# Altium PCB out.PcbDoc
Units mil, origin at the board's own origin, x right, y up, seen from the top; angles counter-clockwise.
Board outline 6000 x 4000 mil, 2 copper layers (Top Layer, Bottom Layer); 0 components, 0 nets, 40 pads, 0 vias.
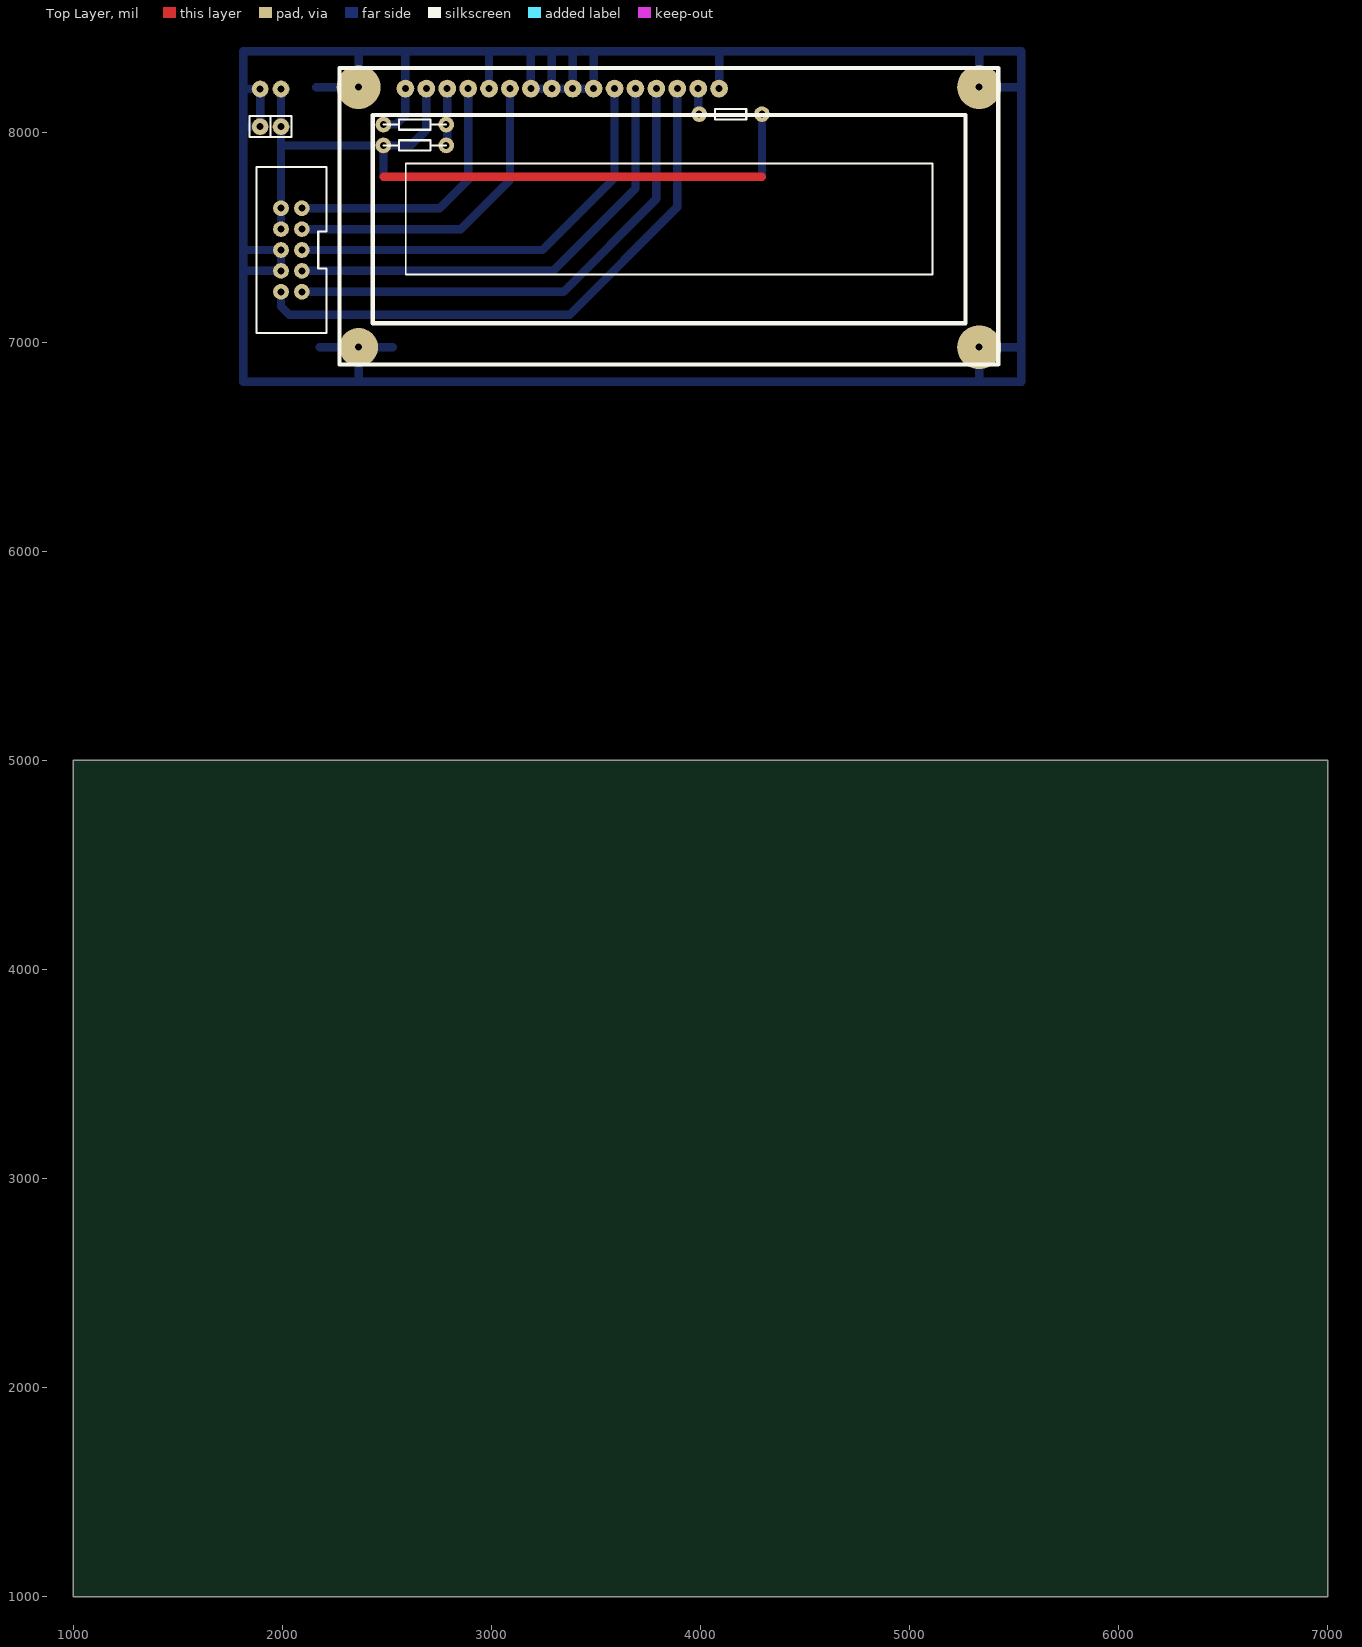
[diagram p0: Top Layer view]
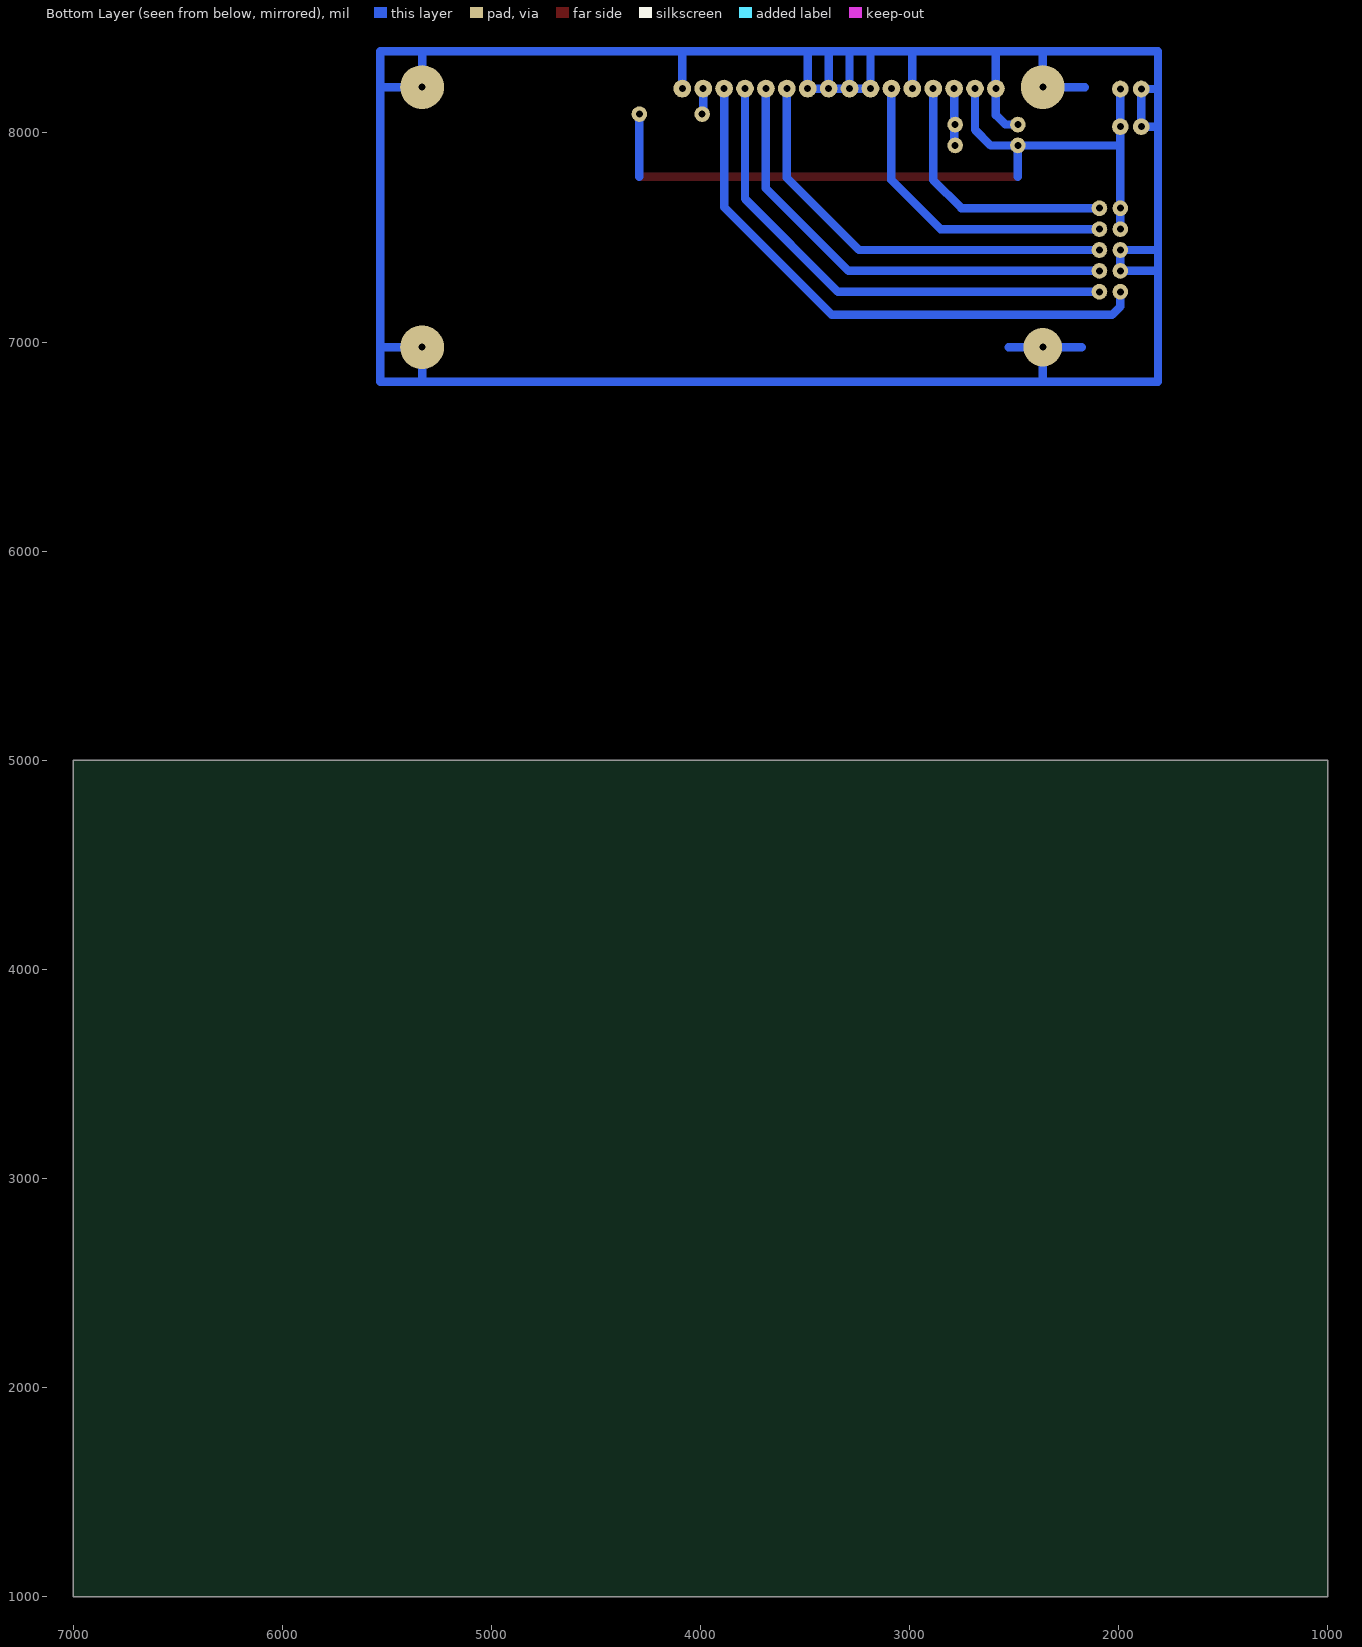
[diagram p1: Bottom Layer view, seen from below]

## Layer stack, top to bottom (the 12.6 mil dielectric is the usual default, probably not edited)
Top Layer: signal copper 1.4
Dielectric: dielectric 12.6, FR-4, Dk 4.8
Bottom Layer: signal copper 1.4

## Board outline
1000,1000 7000,1000 7000,5000 1000,5000

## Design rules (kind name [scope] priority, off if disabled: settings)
Clearance [All] p0: scope1count=1 scope1_0_kind=Board scope1_0_value=Board scope2count=1 scope2_0_kind=Board scope2_0_value=Board commentlength=0 gap=10
Clearance [All] p1: gap=10
ComponentClearance [All] p0: scope1count=1 scope1_0_kind=Board scope1_0_value=Board scope2count=1 scope2_0_kind=Board scope2_0_value=Board commentlength=0 gap=10 collisioncheckmode=3
ComponentClearance [All] p1: gap=10 collisioncheckmode=3 verticalgap=10
DiffPairsRouting [All] p0: scope1count=1 scope1_0_kind=Board scope1_0_value=Board scope2count=1 scope2_0_kind=Board scope2_0_value=Board commentlength=0
FanoutControl Fanout_BGA [All] p0 off: scope1count=1 scope1_0_kind=Board scope1_0_value=Board scope2count=1 scope2_0_kind=Board scope2_0_value=Board commentlength=69 // Protel DXP Scope 1 Expression Was: IsBGA   Fanout_BGA (Default Rule)
FanoutControl Fanout_LCC [All] p0 off: scope1count=1 scope1_0_kind=Board scope1_0_value=Board scope2count=1 scope2_0_kind=Board scope2_0_value=Board commentlength=69 // Protel DXP Scope 1 Expression Was: IsLCC   Fanout_LCC (Default Rule)
FanoutControl Fanout_SOIC [All] p0 off: scope1count=1 scope1_0_kind=Board scope1_0_value=Board scope2count=1 scope2_0_kind=Board scope2_0_value=Board commentlength=71 // Protel DXP Scope 1 Expression Was: IsSOIC   Fanout_SOIC (Default Rule)
FanoutControl Fanout_Small [All] p0 off: scope1count=1 scope1_0_kind=Board scope1_0_value=Board scope2count=1 scope2_0_kind=Board scope2_0_value=Board commentlength=84 // Protel DXP Scope 1 Expression Was: (CompPinCount < 5)   Fanout_Small (Default Rule)
FanoutControl Fanout_Default [All] p0: scope1count=1 scope1_0_kind=Board scope1_0_value=Board scope2count=1 scope2_0_kind=Board scope2_0_value=Board commentlength=30 // Fanout_Default (Default Rule)
Height [All] p0: scope1count=1 scope1_0_kind=Board scope1_0_value=Board scope2count=1 scope2_0_kind=Board scope2_0_value=Board commentlength=0
HoleSize [All] p0: scope1count=1 scope1_0_kind=Board scope1_0_value=Board scope2count=1 scope2_0_kind=Board scope2_0_value=Board commentlength=0 absolutevalues=TRUE maxlimit=100 minlimit=1 maxpercent=80.000 minpercent=20.000
LayerPairs [All] p0: scope1count=1 scope1_0_kind=Board scope1_0_value=Board scope2count=1 scope2_0_kind=Board scope2_0_value=Board commentlength=0 enforce=TRUE
PasteMaskExpansion [All] p0: scope1count=1 scope1_0_kind=Board scope1_0_value=Board scope2count=1 scope2_0_kind=Board scope2_0_value=Board commentlength=0 expansion=0
PlaneClearance [All] p0: scope1count=1 scope1_0_kind=Board scope1_0_value=Board scope2count=1 scope2_0_kind=Board scope2_0_value=Board commentlength=0 clearance=20
PlaneConnect [All] p0: scope1count=1 scope1_0_kind=Board scope1_0_value=Board scope2count=1 scope2_0_kind=Board scope2_0_value=Board commentlength=0 planeconnectstyle=Relief reliefexpansion=20 reliefentries=4 reliefconductorwidth=10 reliefairgap=10
PolygonConnect [All] p0: scope1count=1 scope1_0_kind=Board scope1_0_value=Board scope2count=1 scope2_0_kind=Board scope2_0_value=Board commentlength=0 connectstyle=Relief reliefconductorwidth=10 reliefentries=4 polygonreliefangle="90 Angle"
PolygonConnect [All] p1: connectstyle=Relief reliefconductorwidth=10 reliefentries=4 polygonreliefangle="90 Angle"
RoutingCorners [All] p0: scope1count=1 scope1_0_kind=Board scope1_0_value=Board scope2count=1 scope2_0_kind=Board scope2_0_value=Board commentlength=0 cornerstyle=45-Degree minsetback=100 maxsetback=100
RoutingLayers [All] p0: scope1count=1 scope1_0_kind=Board scope1_0_value=Board scope2count=1 scope2_0_kind=Board scope2_0_value=Board commentlength=0 top layer=Automatic bottom layer=Automatic
RoutingPriority [All] p0: scope1count=1 scope1_0_kind=Board scope1_0_value=Board scope2count=1 scope2_0_kind=Board scope2_0_value=Board commentlength=0
RoutingTopology [All] p0: scope1count=1 scope1_0_kind=Board scope1_0_value=Board scope2count=1 scope2_0_kind=Board scope2_0_value=Board commentlength=0 topology=Shortest
RoutingVias [All] p0: scope1count=1 scope1_0_kind=Board scope1_0_value=Board scope2count=1 scope2_0_kind=Board scope2_0_value=Board commentlength=0 holewidth=28 width=50 viastyle="Through Hole" minholewidth=28 minwidth=50 maxholewidth=28 maxwidth=50
RoutingVias [All] p1: holewidth=28 width=50 viastyle="Through Hole" minholewidth=28 minwidth=50 maxholewidth=28 maxwidth=50
ShortCircuit [All] p0: scope1count=1 scope1_0_kind=Board scope1_0_value=Board scope2count=1 scope2_0_kind=Board scope2_0_value=Board commentlength=0 allowed=FALSE
SolderMaskExpansion [All] p0: scope1count=1 scope1_0_kind=Board scope1_0_value=Board scope2count=1 scope2_0_kind=Board scope2_0_value=Board commentlength=0 expansion=4
SolderMaskExpansion [All] p1: expansion=4
TestPointUsage [All] p0: scope1count=1 scope1_0_kind=Board scope1_0_value=Board scope2count=1 scope2_0_kind=Board scope2_0_value=Board commentlength=0 valid=0 allowmultiple=FALSE
TestPointUsage [All] p1: valid=0 allowmultiple=FALSE
Testpoint [All] p0: scope1count=1 scope1_0_kind=Board scope1_0_value=Board scope2count=1 scope2_0_kind=Board scope2_0_value=Board commentlength=0 side=15 testpointundercomponent=TRUE minsize=40 maxsize=100 preferedsize=60 minholesize=0 maxholesize=40 preferedholesize=32 testpointgrid=1 style=1023 order=0123456789
Testpoint [All] p1: side=15 testpointundercomponent=TRUE minsize=40 maxsize=100 preferedsize=60 minholesize=0 maxholesize=40 preferedholesize=32 testpointgrid=1 style=1023 order=0123456789
UnRoutedNet [All] p0: scope1count=1 scope1_0_kind=Board scope1_0_value=Board scope2count=1 scope2_0_kind=Board scope2_0_value=Board commentlength=0
Width [All] p0: scope1count=1 scope1_0_kind=Board scope1_0_value=Board scope2count=1 scope2_0_kind=Board scope2_0_value=Board commentlength=0 maxlimit=10 minlimit=10 preferedwidth=10
Width [All] p1: maxlimit=10 minlimit=10 preferedwidth=10
18 further rules are at their usual default settings.

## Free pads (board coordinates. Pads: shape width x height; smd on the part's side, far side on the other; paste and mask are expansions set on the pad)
  round 80 hole 33.46: 2(1893,8030) 2(1893,8210) 2(1993,8030) 2(1993,8210)
  round 75 hole 33.46: 2(1993,7240) 2(1993,7340) 2(1993,7440) 2(1993,7540) 2(1993,7640) 2(2093,7240) 2(2093,7340) 2(2093,7440) 2(2093,7540) 2(2093,7640) 2(2483,7940) 2(2483,8040) 2(2783,7940) 2(2783,8040) 2(3993,8090) 2(4293,8090)
  round 185 hole 33.46: 2(2364,6975)
  round 210 hole 33.46: 2(2364,8219) 2(5332,6975) 2(5332,8219)
  round 85 hole 33.46: 2(2588,8212) 2(2688,8212) 2(2788,8212) 2(2888,8212) 2(2988,8212) 2(3088,8212) 2(3188,8212) 2(3288,8212) 2(3388,8212) 2(3488,8212) 2(3588,8212) 2(3688,8212) 2(3788,8212) 2(3888,8212) 2(3988,8212) 2(4088,8212)

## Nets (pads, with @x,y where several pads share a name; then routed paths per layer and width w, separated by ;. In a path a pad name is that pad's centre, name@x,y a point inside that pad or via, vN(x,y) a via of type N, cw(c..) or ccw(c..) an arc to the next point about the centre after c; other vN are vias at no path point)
copper on no net: | length 31268.7
  Top Layer w40: 2483,7790 4293,7790
  Bottom Layer w40: 1813,7340 1993,7340 1993,7440 1813,7440 ; 1813,8030 1893,8030 1893,8210 1813,8210 ; 1993,7240 1993,7170 2033,7130 3373,7130 3888,7645 3888,8212 ; 1993,7540 1993,8210 ; 1993,7940 2613,7940 2688,8015 2688,8212 ; 2093,7240 3343,7240 3788,7685 3788,8212 ; 2093,7340 3293,7340 3688,7735 3688,8212 ; 2093,7440 3243,7440 3588,7785 3588,8212 ; 2093,7540 2853,7540 3088,7775 3088,8212 ; 2093,7640 2753,7640 2888,7775 2888,8212 ; 2162,8219 2364,8219 2364,8381 ; 2178,6975 2528,6975 ; 2364,6819 2364,6975 ; 2483,7790 2483,7940 ; 2483,8040 2543,8040 2588,8085 2588,8385 ; 2788,7945 2788,8212 ; 2988,8212 2988,8385 ; 3188,8385 3188,8212 3488,8212 3488,8385 ; 3288,8212 3288,8385 ; 3388,8212 3388,8385 ; 3988,8085 3988,8212 ; 4088,8212 4088,8385 ; 4293,7790 4293,8090 ; 5332,6821 5332,6975 5528,6975 ; 5332,8381 5332,8219 5524,8219 ; 1813,6810 5533,6810 5533,8390 1813,8390 1813,6810

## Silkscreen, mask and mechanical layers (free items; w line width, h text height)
Top Overlay:
  lines w8: 2589,7323 2589,7854 5109,7854 5109,7323 2589,7323
  lines w10: 1943,8080 1943,7980 2043,7980 ; 2483,7940 2558,7940 ; 2483,8040 2558,8040 ; 2708,7940 2783,7940 ; 2708,8040 2783,8040 ; 3993,8090 4068,8090 ; 4218,8090 4293,8090 ; 2043,7980 2043,8080 1843,8080 1843,7980 2043,7980 ; 1875,7043 2211,7043 2211,7351 2171,7351 2171,7528 2211,7528 2211,7837 1875,7837 1875,7043 ; 2558,7915 2558,7965 2708,7965 2708,7915 2558,7915 ; 2558,8015 2558,8065 2708,8065 2708,8015 2558,8015 ; 4068,8065 4068,8115 4218,8115 4218,8065 4068,8065
  lines w20: 2273,6893 2273,8310 5423,8310 5423,6893 2273,6893 ; 2432,7090 2432,8086 5266,8086 5266,7090 2432,7090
